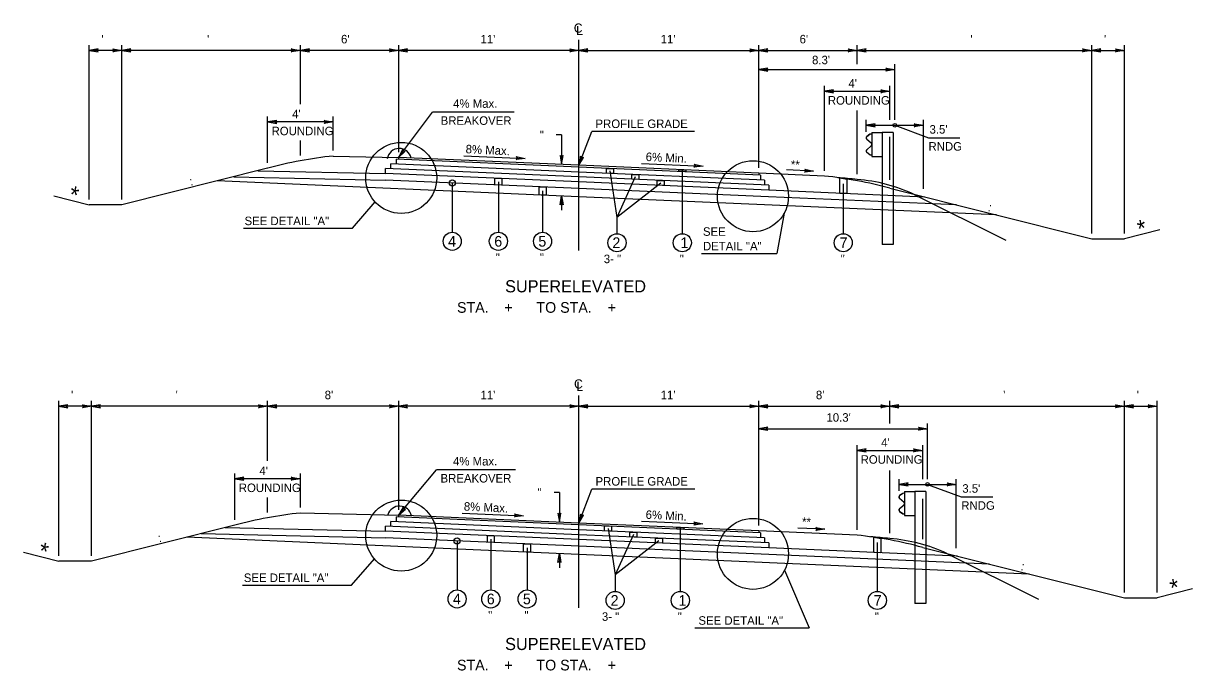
# Model space of a CAD drawing. Extents: x -540 to 1231, y -564 to 421.
# Drawn here: x 755 to 947.4, y -247.3 to -140.9 of the extents above; entities that cross this region are included whole.
import ezdxf

# ---------------------------------------------------------------- set-up
doc = ezdxf.new("R2010")
doc.units = 0
doc.layers.add('1', color=7, linetype='Continuous')
doc.layers.add('Des_ Drain_ Ftrs', color=7, linetype='Continuous')

msp = doc.modelspace()

# ---------------------------------------------------------------- linework, layer by layer
at = {"layer": '1'}
for p, q in [((846.41, -178.19), (846.41, -143.55)), ((765.85, -169.81), (765.85, -144.43)), ((771.24, -145.31), (765.85, -145.31)), ((771.24, -169.81), (771.24, -144.43)), ((800.61, -145.31), (771.24, -145.31)), ((800.61, -154.13), (800.61, -144.43)), ((816.78, -145.31), (800.61, -145.31)), ((816.78, -162.04), (816.78, -144.43)), ((846.41, -145.31), (816.78, -145.31)), ((846.41, -145.31), (876.05, -145.31)), ((876.05, -164.63), (876.05, -144.43)), ((876.05, -145.31), (892.21, -145.31)), ((892.21, -147.59), (892.21, -144.43)), ((892.21, -145.31), (930.8, -145.31)), ((930.8, -175.41), (930.8, -144.43)), ((930.8, -145.31), (936.19, -145.31)), ((936.19, -175.41), (936.19, -144.43)), ((898.4, -156.74), (898.4, -147.59)), ((876.04, -148.47), (898.4, -148.47)), ((886.82, -165.1), (886.82, -151.16)), ((897.6, -156.74), (897.6, -151.16)), ((886.82, -152.04), (897.6, -152.04)), ((816.77, -162.92), (822.32, -155.45)), ((835.79, -155.45), (822.32, -155.45)), ((892.21, -165.65), (892.21, -155.21)), ((795.22, -163.82), (795.22, -156.2)), ((806, -157.08), (795.22, -157.08)), ((806, -161.8), (806, -156.2)), ((893.71, -158.7), (893.71, -156.74)), ((893.71, -157.62), (903.1, -157.62)), ((898.4, -157.62), (903.96, -159.7)), ((903.1, -168.09), (903.1, -156.74)), ((843.58, -159.21), (842.7, -159.21)), ((843.58, -159.21), (843.58, -164.09)), ((846.41, -164.21), (848.55, -158.67)), ((865.47, -158.67), (848.55, -158.67)), ((894.31, -159.09), (893.79, -159.48)), ((894.32, -159.12), (893.81, -159.51)), ((894.62, -159.04), (894.31, -159.09)), ((894.62, -159.07), (894.32, -159.12)), ((894.62, -158.81), (894.62, -162.74)), ((894.62, -158.81), (896.31, -158.81)), ((896.31, -158.81), (896.31, -177.21)), ((898.14, -158.81), (896.31, -158.81)), ((897.6, -166.62), (897.6, -159.55)), ((898.14, -158.81), (898.14, -177.21)), ((800.61, -162.58), (800.61, -160.14)), ((893.78, -159.91), (894.51, -160.55)), ((894.51, -161), (893.78, -161.64)), ((893.8, -159.89), (894.53, -160.53)), ((894.53, -161.02), (893.8, -161.66)), ((894.6, -160.74), (894.6, -160.81)), ((894.62, -160.74), (894.62, -160.81)), ((903.96, -159.7), (909.12, -159.7)), ((806, -162.68), (816.77, -162.92)), ((846.41, -164.51), (816.43, -163.2)), ((816.43, -164.01), (816.43, -163.2)), ((846.41, -164.21), (816.77, -162.92)), ((816.77, -162.92), (816.77, -163.22)), ((827.49, -162.64), (837.6, -163.08)), ((893.79, -162.07), (894.31, -162.46)), ((893.81, -162.04), (894.32, -162.43)), ((894.31, -162.46), (894.62, -162.51)), ((894.32, -162.43), (894.62, -162.48)), ((894.62, -162.74), (896.31, -162.74)), ((795.22, -164.7), (771.24, -170.69)), ((793.63, -165.09), (814.6, -165.55)), ((846.41, -166.13), (814.59, -164.74)), ((814.59, -165.55), (814.59, -164.74)), ((814.59, -164.74), (814.59, -164.74)), ((846.41, -165.32), (815.51, -163.97)), ((815.51, -164.78), (815.51, -163.97)), ((876.05, -165.51), (846.41, -164.21)), ((876.29, -165.82), (846.41, -164.51)), ((876.99, -166.66), (846.41, -165.32)), ((851.54, -165.14), (852.7, -172.77)), ((856.74, -163.89), (866.85, -164.33)), ((863.44, -165.12), (863.44, -175.45)), ((885.05, -165.16), (880.56, -164.96)), ((846.41, -169.37), (786.92, -166.77)), ((789.66, -166.09), (814.59, -166.63)), ((846.41, -168.02), (814.59, -166.63)), ((846.41, -166.94), (814.6, -165.55)), ((825.59, -167.11), (825.59, -175.22)), ((833.18, -166.9), (833.18, -175.22)), ((877.69, -167.5), (846.41, -166.13)), ((877.7, -168.31), (846.41, -166.94)), ((855.71, -166.13), (852.7, -172.77)), ((859.89, -167.14), (852.7, -172.77)), ((886.82, -165.98), (876.05, -165.51)), ((876.05, -165.51), (876.05, -165.81)), ((876.29, -165.82), (876.29, -166.63)), ((876.99, -166.66), (876.99, -167.47)), ((889.92, -167.23), (889.92, -175.45)), ((893.71, -166.76), (893.71, -166.76)), ((760.03, -169.23), (765.85, -170.69)), ((840.45, -168.43), (840.45, -175.22)), ((843.58, -169.24), (843.58, -171.61)), ((877.65, -169.38), (846.41, -168.02)), ((877.69, -167.5), (877.69, -168.31)), ((903.36, -169.43), (877.69, -168.31)), ((897.6, -167.99), (930.8, -176.29)), ((901.6, -168.99), (916.65, -176.51)), ((771.24, -170.69), (765.85, -170.69)), ((809.16, -174.55), (812.9, -170.23)), ((915.12, -172.37), (846.41, -169.37)), ((908.58, -170.73), (877.65, -169.38)), ((852.7, -172.77), (852.7, -175.45)), ((880.2, -172.07), (879.02, -178.72)), ((791.23, -174.55), (809.16, -174.55)), ((942.01, -174.83), (936.19, -176.29)), ((930.8, -176.29), (936.19, -176.29)), ((866.61, -178.72), (879.02, -178.72)), ((898.14, -177.21), (896.31, -177.21)), ((760.86, -228.41), (760.86, -202.94)), ((766.25, -203.82), (760.86, -203.82)), ((766.25, -228.41), (766.25, -202.94)), ((795.22, -203.82), (766.25, -203.82)), ((795.22, -212.83), (795.22, -202.94)), ((816.78, -203.82), (795.22, -203.82)), ((816.78, -220.86), (816.78, -202.94)), ((846.41, -203.82), (816.78, -203.82)), ((846.41, -237), (846.41, -202.06)), ((846.41, -203.82), (876.05, -203.82)), ((876.05, -223.45), (876.05, -202.94)), ((876.05, -203.82), (897.6, -203.82)), ((897.6, -206.64), (897.6, -202.94)), ((897.6, -203.82), (936.19, -203.82)), ((936.19, -234.46), (936.19, -202.94)), ((936.19, -203.82), (941.58, -203.82)), ((941.58, -234.46), (941.58, -202.94)), ((876.05, -207.52), (903.8, -207.52)), ((903.8, -215.8), (903.8, -206.64)), ((892.21, -224.15), (892.21, -210.22)), ((892.21, -211.1), (902.99, -211.1)), ((902.99, -215.8), (902.99, -210.22)), ((789.83, -222.51), (789.83, -214.88)), ((800.61, -220.5), (800.61, -214.88)), ((816.77, -221.74), (823.03, -214.27)), ((836, -214.27), (823.03, -214.27)), ((897.6, -224.71), (897.6, -214.39)), ((800.61, -215.76), (789.83, -215.76)), ((899.1, -217.75), (899.1, -215.8)), ((899.1, -216.68), (908.49, -216.68)), ((903.8, -216.68), (909.35, -218.75)), ((908.49, -227.16), (908.49, -215.8)), ((795.22, -221.28), (795.22, -218.83)), ((843.22, -218.01), (842.34, -218.01)), ((843.22, -218.01), (843.22, -222.89)), ((846.41, -223.03), (848.56, -217.46)), ((865.48, -217.46), (848.56, -217.46)), ((899.17, -218.97), (899.9, -219.6)), ((899.7, -218.15), (899.18, -218.53)), ((899.19, -218.94), (899.92, -219.58)), ((899.71, -218.17), (899.2, -218.56)), ((900.02, -218.09), (899.7, -218.15)), ((900.02, -218.12), (899.71, -218.17)), ((900.02, -217.86), (900.02, -221.79)), ((900.02, -217.86), (901.7, -217.86)), ((901.7, -217.86), (901.7, -236.26)), ((903.53, -217.86), (901.7, -217.86)), ((902.99, -225.67), (902.99, -219.03)), ((903.53, -217.86), (903.53, -236.26)), ((909.35, -218.75), (914.51, -218.75)), ((899.9, -220.05), (899.17, -220.69)), ((899.18, -221.12), (899.7, -221.51)), ((899.92, -220.08), (899.19, -220.71)), ((899.2, -221.1), (899.71, -221.48)), ((899.99, -219.79), (899.99, -219.87)), ((900.02, -219.79), (900.02, -219.87)), ((800.61, -221.38), (816.77, -221.74)), ((846.41, -224.14), (815.51, -222.79)), ((815.51, -223.6), (815.51, -222.79)), ((846.41, -223.33), (816.43, -222.02)), ((816.43, -222.83), (816.43, -222.02)), ((846.41, -223.03), (816.77, -221.74)), ((816.77, -221.74), (816.77, -222.04)), ((827.2, -221.39), (837.31, -221.84)), ((876.05, -224.33), (846.41, -223.03)), ((856.72, -222.73), (866.83, -223.17)), ((899.7, -221.51), (900.02, -221.57)), ((899.71, -221.48), (900.02, -221.54)), ((900.02, -221.79), (901.7, -221.79)), ((789.84, -223.39), (766.25, -229.29)), ((784.27, -224.78), (814.59, -225.45)), ((788.24, -223.79), (814.59, -224.37)), ((846.41, -224.95), (814.59, -223.56)), ((814.59, -224.37), (814.59, -223.56)), ((846.41, -225.76), (814.59, -224.37)), ((876.29, -224.63), (846.41, -223.33)), ((876.99, -225.47), (846.41, -224.14)), ((877.69, -226.31), (846.41, -224.95)), ((851.23, -223.94), (852.4, -231.57)), ((855.41, -224.93), (852.4, -231.57)), ((863.12, -223.93), (863.12, -234.27)), ((892.21, -225.03), (876.05, -224.33)), ((876.05, -224.33), (876.05, -224.63)), ((876.29, -224.63), (876.29, -225.44)), ((886.92, -224.05), (882.43, -223.86)), ((846.41, -228.18), (781.94, -225.37)), ((846.41, -226.84), (814.59, -225.45)), ((826.39, -225.98), (826.39, -234.03)), ((831.94, -225.69), (831.94, -234.03)), ((877.69, -227.12), (846.41, -225.76)), ((877.69, -228.2), (846.41, -226.84)), ((859.58, -225.94), (852.4, -231.57)), ((876.99, -225.47), (876.99, -226.28)), ((877.69, -226.31), (877.69, -227.12)), ((895.53, -226.25), (895.53, -234.27)), ((899.1, -225.81), (899.1, -225.81)), ((755.04, -227.83), (760.86, -229.29)), ((837.91, -227.12), (837.91, -234.03)), ((843.22, -228.04), (843.22, -230.41)), ((920.5, -231.42), (846.41, -228.18)), ((908.74, -228.48), (877.69, -227.12)), ((913.97, -229.79), (877.69, -228.2)), ((902.99, -227.04), (936.19, -235.34)), ((906.99, -228.04), (922.04, -235.57)), ((766.25, -229.29), (760.86, -229.29)), ((809.04, -233.23), (812.78, -228.91)), ((880.25, -230.8), (884.3, -240.26)), ((852.4, -231.57), (852.4, -234.27)), ((791.11, -233.23), (809.04, -233.23)), ((947.4, -233.88), (941.58, -235.34)), ((903.53, -236.26), (901.7, -236.26)), ((936.19, -235.34), (941.57, -235.34)), ((865.52, -240.26), (884.3, -240.26))]:
    msp.add_line(p, q, dxfattribs=at)
for points in [[(850.96, -164.71), (852.11, -164.76), (852.11, -165.57), (850.96, -165.52)], [(862.87, -164.93), (864.02, -164.98), (864.02, -165.28), (862.87, -165.23)], [(832.6, -166.34), (833.75, -166.39), (833.75, -167.47), (832.6, -167.42)], [(855.14, -165.7), (856.29, -165.75), (856.29, -166.56), (855.14, -166.51)], [(859.31, -166.7), (860.46, -166.75), (860.46, -167.55), (859.31, -167.5)], [(889.35, -166.29), (890.49, -166.46), (890.49, -168.87), (889.35, -168.82)], [(839.87, -167.73), (841.02, -167.78), (841.02, -169.13), (839.87, -169.08)], [(850.66, -223.52), (851.81, -223.57), (851.81, -224.38), (850.66, -224.33)], [(854.83, -224.51), (855.98, -224.56), (855.98, -225.37), (854.83, -225.32)], [(862.54, -223.74), (863.69, -223.79), (863.69, -224.08), (862.54, -224.03)], [(831.37, -225.1), (832.51, -225.15), (832.51, -226.23), (831.37, -226.18)], [(837.33, -226.44), (838.48, -226.49), (838.48, -227.84), (837.33, -227.79)], [(859.01, -225.5), (860.16, -225.55), (860.16, -226.36), (859.01, -226.31)], [(894.96, -225.37), (896.1, -225.55), (896.1, -227.93), (894.96, -227.88)]]:
    msp.add_lwpolyline(points, close=True, dxfattribs=at)
for centre, radius in [((898.4, -157.62), 0.3), ((817.2, -166.28), 5.84), ((875.07, -169.29), 5.84), ((825.59, -167.11), 0.5), ((825.59, -176.7), 1.49), ((833.18, -176.7), 1.49), ((840.45, -176.7), 1.49), ((852.7, -176.94), 1.49), ((863.44, -176.94), 1.49), ((889.92, -176.94), 1.49), ((903.8, -216.68), 0.3), ((817.2, -225.1), 5.84), ((875.07, -228.1), 5.84), ((826.39, -225.98), 0.5), ((826.39, -235.52), 1.49), ((831.94, -235.52), 1.49), ((837.91, -235.52), 1.49), ((852.4, -235.76), 1.49), ((863.12, -235.76), 1.49), ((895.53, -235.76), 1.49)]:
    msp.add_circle(centre, radius, dxfattribs=at)
for centre, radius, start, end in [((893.96, -159.7), 0.278, 126.9799, 229.021), ((893.96, -159.7), 0.249, 126.9799, 229.021), ((816.88, -163.42), 1.99, 11.9626, 172.1146), ((894.35, -160.74), 0.249, 0, 49.0365), ((894.35, -160.81), 0.249, 310.9635, 0), ((894.35, -160.74), 0.278, 0, 49.0365), ((894.35, -160.81), 0.278, 310.9635, 0), ((812.9, -229.52), 67.19, 95.8911, 105.2497), ((893.96, -161.85), 0.278, 130.979, 233.0201), ((893.96, -161.85), 0.249, 130.979, 233.0201), ((879.94, -232.81), 67.19, 74.7602, 84.1188), ((881.39, -267.2), 101.24, 83.8633, 85.6775), ((890.09, -193.82), 27.37, 65.1374, 85.5513), ((899.35, -218.76), 0.278, 126.9799, 229.021), ((899.35, -218.76), 0.249, 126.9799, 229.021), ((816.93, -222.25), 2, 12.248, 163.8505), ((899.35, -220.9), 0.278, 130.979, 233.0201), ((899.35, -220.9), 0.249, 130.979, 233.0201), ((899.74, -219.79), 0.249, 0, 49.0365), ((899.74, -219.87), 0.249, 310.9635, 0), ((899.74, -219.79), 0.278, 0, 49.0365), ((899.74, -219.87), 0.278, 310.9635, 0), ((807.51, -288.22), 67.19, 95.8897, 105.2483), ((885.33, -291.87), 67.19, 74.7602, 84.1188), ((886.78, -326.25), 101.24, 83.8633, 85.6775), ((895.48, -252.87), 27.37, 65.1374, 85.5513)]:
    msp.add_arc(centre, radius, start, end, dxfattribs=at)
at = {"layer": 'Des_ Drain_ Ftrs'}
for points in [[(765.85, -145.31), (767.34, -145.56), (767.05, -145.31), (767.34, -145.06)], [(771.24, -145.31), (769.75, -145.56), (770.05, -145.31), (769.75, -145.06)], [(771.24, -145.31), (772.73, -145.56), (772.43, -145.31), (772.73, -145.06)], [(800.61, -145.31), (799.12, -145.56), (799.42, -145.31), (799.12, -145.06)], [(800.61, -145.31), (802.1, -145.56), (801.8, -145.31), (802.1, -145.06)], [(816.78, -145.31), (815.29, -145.56), (815.58, -145.31), (815.29, -145.06)], [(816.78, -145.31), (818.26, -145.56), (817.97, -145.31), (818.26, -145.06)], [(846.41, -145.31), (844.92, -145.56), (845.22, -145.31), (844.92, -145.06)], [(846.41, -145.31), (847.9, -145.56), (847.6, -145.31), (847.9, -145.06)], [(876.05, -145.31), (874.56, -145.56), (874.85, -145.31), (874.56, -145.06)], [(876.05, -145.31), (877.53, -145.56), (877.24, -145.31), (877.53, -145.06)], [(892.21, -145.31), (890.72, -145.56), (891.02, -145.31), (890.72, -145.06)], [(892.21, -145.31), (893.7, -145.56), (893.4, -145.31), (893.7, -145.06)], [(930.8, -145.31), (929.31, -145.56), (929.61, -145.31), (929.31, -145.06)], [(930.8, -145.31), (932.29, -145.56), (931.99, -145.31), (932.29, -145.06)], [(936.19, -145.31), (934.7, -145.56), (934.99, -145.31), (934.7, -145.06)], [(876.04, -148.47), (877.53, -148.72), (877.24, -148.47), (877.53, -148.22)], [(898.4, -148.47), (896.92, -148.72), (897.21, -148.47), (896.92, -148.22)], [(886.82, -152.04), (888.31, -152.29), (888.02, -152.04), (888.31, -151.79)], [(897.6, -152.04), (896.11, -152.29), (896.41, -152.04), (896.11, -151.79)], [(795.22, -157.08), (796.71, -157.33), (796.42, -157.08), (796.71, -156.83)], [(806, -157.08), (804.51, -157.33), (804.81, -157.08), (804.51, -156.83)], [(893.71, -157.62), (895.2, -157.87), (894.91, -157.62), (895.2, -157.38)], [(903.1, -157.62), (901.61, -157.87), (901.9, -157.62), (901.61, -157.38)], [(816.77, -162.92), (817.86, -161.87), (817.48, -161.96), (817.46, -161.58)], [(837.6, -163.08), (836.1, -163.27), (836.41, -163.03), (836.12, -162.77)], [(843.58, -164.09), (843.83, -162.6), (843.58, -162.9), (843.33, -162.6)], [(846.41, -164.21), (847.18, -162.91), (846.84, -163.1), (846.71, -162.73)], [(866.85, -164.33), (865.35, -164.51), (865.66, -164.28), (865.37, -164.02)], [(885.05, -165.16), (883.56, -165.34), (883.86, -165.11), (883.58, -164.85)], [(843.58, -169.24), (843.83, -170.73), (843.58, -170.44), (843.33, -170.73)], [(760.86, -203.82), (762.35, -204.07), (762.06, -203.82), (762.35, -203.57)], [(766.25, -203.82), (764.76, -204.07), (765.06, -203.82), (764.76, -203.57)], [(766.25, -203.82), (767.74, -204.07), (767.45, -203.82), (767.74, -203.57)], [(795.22, -203.82), (793.73, -204.07), (794.03, -203.82), (793.73, -203.57)], [(795.22, -203.82), (796.71, -204.07), (796.42, -203.82), (796.71, -203.57)], [(816.78, -203.82), (815.29, -204.07), (815.58, -203.82), (815.29, -203.57)], [(816.78, -203.82), (818.26, -204.07), (817.97, -203.82), (818.26, -203.57)], [(846.41, -203.82), (844.92, -204.07), (845.22, -203.82), (844.92, -203.57)], [(846.41, -203.82), (847.9, -204.07), (847.6, -203.82), (847.9, -203.57)], [(876.05, -203.82), (874.56, -204.07), (874.85, -203.82), (874.56, -203.57)], [(876.05, -203.82), (877.53, -204.07), (877.24, -203.82), (877.53, -203.57)], [(897.6, -203.82), (896.11, -204.07), (896.41, -203.82), (896.11, -203.57)], [(897.6, -203.82), (899.09, -204.07), (898.79, -203.82), (899.09, -203.57)], [(936.19, -203.82), (934.7, -204.07), (935, -203.82), (934.7, -203.57)], [(936.19, -203.82), (937.68, -204.07), (937.38, -203.82), (937.68, -203.57)], [(941.58, -203.82), (940.09, -204.07), (940.39, -203.82), (940.09, -203.57)], [(876.05, -207.52), (877.53, -207.77), (877.24, -207.52), (877.53, -207.27)], [(903.8, -207.52), (902.31, -207.77), (902.6, -207.52), (902.31, -207.27)], [(892.21, -211.1), (893.7, -211.34), (893.4, -211.1), (893.7, -210.85)], [(902.99, -211.1), (901.5, -211.34), (901.79, -211.1), (901.5, -210.85)], [(789.83, -215.76), (791.32, -216.01), (791.03, -215.76), (791.32, -215.51)], [(800.61, -215.76), (799.12, -216.01), (799.42, -215.76), (799.12, -215.51)], [(899.1, -216.68), (900.59, -216.93), (900.3, -216.68), (900.59, -216.43)], [(908.49, -216.68), (907, -216.93), (907.29, -216.68), (907, -216.43)], [(816.77, -221.74), (817.92, -220.75), (817.54, -220.82), (817.54, -220.44)], [(837.31, -221.84), (835.81, -222.02), (836.12, -221.78), (835.83, -221.52)], [(843.22, -222.89), (843.46, -221.4), (843.22, -221.7), (842.97, -221.4)], [(846.41, -223.03), (847.18, -221.73), (846.84, -221.92), (846.71, -221.55)], [(866.83, -223.17), (865.33, -223.36), (865.64, -223.12), (865.35, -222.86)], [(886.92, -224.05), (885.42, -224.24), (885.73, -224), (885.44, -223.74)], [(843.22, -228.04), (843.46, -229.53), (843.22, -229.24), (842.97, -229.53)]]:
    msp.add_lwpolyline(points, close=True, dxfattribs=at)

# ---------------------------------------------------------------- texts
at = {"layer": '1'}
for s, height, p in [(" '", 1.4, (767.35, -144.16)), ("  '", 1.4, (784.23, -144.16)), ("6'", 1.4, (807.3, -144.16)), ("11'", 1.4, (830.25, -144.16)), ("11'", 1.4, (859.88, -144.16)), ("6'", 1.4, (882.74, -144.16)), ("  '", 1.4, (909.81, -144.16)), (" '", 1.4, (932.3, -144.16)), ("8.3'", 1.4, (884.79, -147.59)), ("4'", 1.4, (890.78, -151.43)), ('4% Max.', 1.4, (825.74, -154.75)), ('ROUNDING', 1.4, (887.39, -154.23)), ("4'", 1.4, (799.26, -156.46)), ('BREAKOVER', 1.4, (823.69, -157.55)), ('PROFILE GRADE', 1.4, (849.16, -158.08)), ("3.5'", 1.4, (904.12, -159)), ('ROUNDING', 1.4, (795.87, -159.26)), ('RNDG', 1.4, (903.95, -161.8)), ('SEE DETAIL "A"', 1.4, (791.42, -174.05)), ('SEE', 1.4, (866.84, -175.8)), ('4', 1.75, (824.91, -177.58)), ('6', 1.75, (832.51, -177.58)), ('5', 1.75, (839.76, -177.58)), ('2', 1.75, (851.95, -177.81)), ('1', 1.75, (863.14, -177.81)), ('DETAIL "A"', 1.4, (866.84, -178.2)), ('7', 1.75, (889.33, -177.81)), (' "', 1.4, (832.23, -180.06)), (' "', 1.4, (839.5, -180.06)), ('3- "', 1.4, (850.52, -180.3)), (' "', 1.4, (862.5, -180.3)), (' "', 1.4, (888.98, -180.3)), ('SUPERELEVATED', 2, (834.29, -185.1)), ('STA.    +      TO STA.    +     ', 1.75, (826.38, -188.46)), (" '", 1.4, (762.36, -202.67)), ("  '", 1.4, (779.04, -202.67)), ("8'", 1.4, (804.61, -202.67)), ("11'", 1.4, (830.25, -202.67)), ("11'", 1.4, (859.88, -202.67)), ("8'", 1.4, (885.43, -202.67)), ("  '", 1.4, (915.2, -202.67)), (" '", 1.4, (937.69, -202.67)), ("10.3'", 1.4, (887.16, -206.37)), ("4'", 1.4, (896.17, -210.48)), ('4% Max.', 1.4, (825.72, -213.57)), ('ROUNDING', 1.4, (892.78, -213.28)), ("4'", 1.4, (793.87, -215.14)), ('BREAKOVER', 1.4, (823.67, -216.37)), ('ROUNDING', 1.4, (790.48, -217.94)), ('PROFILE GRADE', 1.4, (849.17, -216.88)), ("3.5'", 1.4, (909.51, -218.05)), ('RNDG', 1.4, (909.34, -220.85)), ('SEE DETAIL "A"', 1.4, (791.3, -232.73)), ('4', 1.75, (825.71, -236.39)), ('6', 1.75, (831.28, -236.39)), ('5', 1.75, (837.22, -236.39)), ('2', 1.75, (851.65, -236.63)), ('1', 1.75, (862.82, -236.63)), ('7', 1.75, (894.94, -236.63)), (' "', 1.4, (831, -238.88)), (' "', 1.4, (836.96, -238.88)), ('3- "', 1.4, (850.22, -239.11)), (' "', 1.4, (862.17, -239.11)), ('SEE DETAIL "A"', 1.4, (866.1, -239.76)), ('  "', 1.4, (894.09, -239.11)), ('SUPERELEVATED', 2, (834.29, -243.92)), ('STA.    +      TO STA.    +     ', 1.75, (826.38, -247.27))]:
    msp.add_text(s, height=height, dxfattribs=at).set_placement(p)
for s, height, rotation, p in [('  "', 1.4, 0.1438, (838.97, -159.91)), ('8% Max.', 1.4, 357.3769, (827.77, -162.22)), ('6% Min.', 1.4, 357.3725, (857.4, -163.49)), ('**', 1.4, 357.2506, (881.27, -164.75)), (' : ', 1.4, 14.2282, (782.05, -167.71)), ('*', 2.8, 347.1521, (762.34, -170.26)), (' : ', 1.4, 345.7718, (913.15, -171.59)), ('*', 2.8, 12.8479, (938.65, -176.1)), ('  "', 1.4, 0.1438, (838.6, -218.72)), ('8% Max.', 1.4, 357.3761, (827.48, -220.98)), ('6% Min.', 1.4, 357.3732, (857.39, -222.33)), ('**', 1.4, 357.216, (883.11, -223.49)), ('*', 2.8, 347.1521, (757.35, -228.86)), (' : ', 1.4, 14.2282, (776.86, -226.35)), (' : ', 1.4, 345.7718, (918.54, -230.64)), ('*', 2.8, 12.8479, (944.04, -235.15))]:
    msp.add_text(s, height=height, rotation=rotation, dxfattribs=at).set_placement(p)
at = {"layer": 'Des_ Drain_ Ftrs'}
for s, p in [('C', (845.59, -142.39)), ('L', (845.98, -142.79)), ('C', (845.63, -200.91)), ('L', (846.02, -201.31))]:
    msp.add_text(s, height=1.5, dxfattribs=at).set_placement(p)

doc.saveas('drawing.dxf')
